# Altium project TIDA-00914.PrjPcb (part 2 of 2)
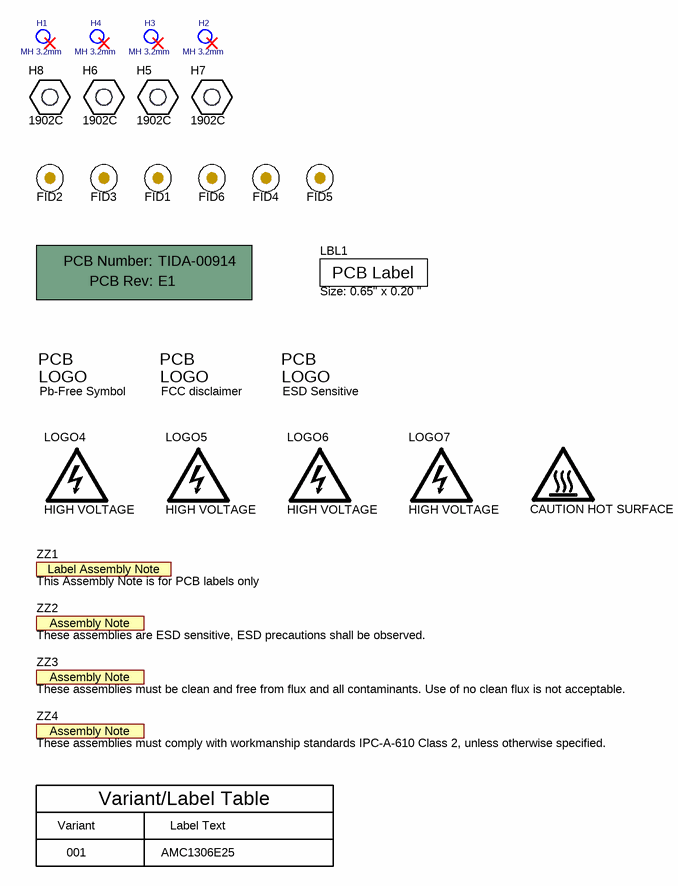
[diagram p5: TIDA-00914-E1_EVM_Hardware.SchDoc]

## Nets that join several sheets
3V3: TIDA-00914-E1_Gate drivers (21 pins), TIDA-00914-E1_IGBT Module, Temp and DC link sense (6 pins), TIDA-00914-E1_Current sense, MCU Interface (15 pins)
GND: TIDA-00914-E1_Gate drivers (35 pins), TIDA-00914-E1_IGBT Module, Temp and DC link sense (6 pins), TIDA-00914-E1_Current sense, MCU Interface (27 pins)
GND_UT: TIDA-00914-E1_Gate drivers (7 pins), TIDA-00914-E1_IGBT Module, Temp and DC link sense (C74.2 R112.1 TP18.1 U24.10), TIDA-00914-E1_Current sense, MCU Interface (5 pins)
GND_VT: TIDA-00914-E1_Gate drivers (7 pins), TIDA-00914-E1_IGBT Module, Temp and DC link sense (C73.2 R32.1 TP16.1 U24.6)
GND_WT: TIDA-00914-E1_Gate drivers (7 pins), TIDA-00914-E1_IGBT Module, Temp and DC link sense (5 pins), TIDA-00914-E1_Current sense, MCU Interface (5 pins)
VCC: TIDA-00914-E1_Gate drivers (19 pins), TIDA-00914-E1_IGBT Module, Temp and DC link sense (R110.1)
VCC_UT: TIDA-00914-E1_Gate drivers (6 pins), TIDA-00914-E1_Current sense, MCU Interface (C21.2 U22.2)
VCC_WT: TIDA-00914-E1_Gate drivers (6 pins), TIDA-00914-E1_Current sense, MCU Interface (C71.2 U20.2)
VDC-: TIDA-00914-E1_Gate drivers (22 pins), TIDA-00914-E1_IGBT Module, Temp and DC link sense (44 pins)
BRAKE_IGBT_GATE: TIDA-00914-E1_Gate drivers (R71.2 R94.2), TIDA-00914-E1_IGBT Module, Temp and DC link sense (C78.1 Q1.1 R96.2)
MCLK: TIDA-00914-E1_IGBT Module, Temp and DC link sense (R55.2 R58.2 TP2.1 TP15.1), TIDA-00914-E1_Current sense, MCU Interface (5 pins)
MDATA_TMP: TIDA-00914-E1_IGBT Module, Temp and DC link sense (R59.2 TP3.1), TIDA-00914-E1_Current sense, MCU Interface (J1.24)
MDATA_VDC: TIDA-00914-E1_IGBT Module, Temp and DC link sense (R56.2 TP1.1), TIDA-00914-E1_Current sense, MCU Interface (J1.23)
PWM_BRAKE+: TIDA-00914-E1_Gate drivers (R8.2), TIDA-00914-E1_Current sense, MCU Interface (J1.8)
PWM_UB+: TIDA-00914-E1_Gate drivers (R144.2), TIDA-00914-E1_Current sense, MCU Interface (J1.2)
PWM_UT+: TIDA-00914-E1_Gate drivers (R143.2), TIDA-00914-E1_Current sense, MCU Interface (J1.3)
PWM_VB+: TIDA-00914-E1_Gate drivers (R141.2), TIDA-00914-E1_Current sense, MCU Interface (J1.4)
PWM_VT+: TIDA-00914-E1_Gate drivers (R142.2), TIDA-00914-E1_Current sense, MCU Interface (J1.5)
PWM_WB+: TIDA-00914-E1_Gate drivers (R139.2), TIDA-00914-E1_Current sense, MCU Interface (J1.6)
PWM_WT+: TIDA-00914-E1_Gate drivers (R140.2), TIDA-00914-E1_Current sense, MCU Interface (J1.7)
U_BOT: TIDA-00914-E1_Gate drivers (R23.2 R25.2 R27.2), TIDA-00914-E1_IGBT Module, Temp and DC link sense (C75.1 R12.2 TP19.1 U24.11)
U_PHASE: TIDA-00914-E1_IGBT Module, Temp and DC link sense (J4.1 R120.2), TIDA-00914-E1_Current sense, MCU Interface (R80.1)
U_PHASE_REF: TIDA-00914-E1_IGBT Module, Temp and DC link sense (5 pins), TIDA-00914-E1_Current sense, MCU Interface (R79.1)
U_TOP: TIDA-00914-E1_Gate drivers (R15.2 R18.2 R21.2), TIDA-00914-E1_IGBT Module, Temp and DC link sense (C74.1 R112.2 TP17.1 U24.9)
V_BOT: TIDA-00914-E1_Gate drivers (R35.2 R37.2 R39.2), TIDA-00914-E1_IGBT Module, Temp and DC link sense (C76.1 R38.2 TP21.1 U24.7)
V_TOP: TIDA-00914-E1_Gate drivers (R29.2 R31.2 R33.2), TIDA-00914-E1_IGBT Module, Temp and DC link sense (C73.1 R32.2 TP14.1 U24.5)
W_BOT: TIDA-00914-E1_Gate drivers (R9.2 R11.2 R13.2), TIDA-00914-E1_IGBT Module, Temp and DC link sense (C77.1 R26.2 TP23.1 U24.3)
W_PHASE: TIDA-00914-E1_IGBT Module, Temp and DC link sense (J4.3 R118.2), TIDA-00914-E1_Current sense, MCU Interface (R86.1)
W_PHASE_REF: TIDA-00914-E1_IGBT Module, Temp and DC link sense (6 pins), TIDA-00914-E1_Current sense, MCU Interface (R85.1)
W_TOP: TIDA-00914-E1_Gate drivers (R3.2 R17.2 R19.2), TIDA-00914-E1_IGBT Module, Temp and DC link sense (C72.1 R20.2 TP12.1 U24.1)

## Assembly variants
AMC1306E25: not fitted C10 C11 C12 C13 C15 C16 C18 C20 C22 C28 C31 C37 C39 C43 C45 C48 C49 C50 C51 C52 C53 C54 C56 C72 C73 C74 C75 C76 C77 C78 C81 C83 C84 C92 C94 D2 D3 D4 D5 D6 D7 D9 D10 D11 J3 J5 J6 J13 Q1 R2 R5 R8 R11 R14 R17 R18 R22 R25 R28 R31 R34 R37 R40 R71 R81 R90 R94 R96 R99 R100 R101 R102 R103 R105 U10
